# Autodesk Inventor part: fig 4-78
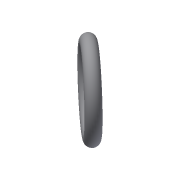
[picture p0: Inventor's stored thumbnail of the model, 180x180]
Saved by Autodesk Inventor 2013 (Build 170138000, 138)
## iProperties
Created: 2012-07
Part Number: fig 4-78
Material: Generic
Document SubType Name: Modeling
Designer: CADCIM
Density: 1 g/cm^3
Author: CADCIM
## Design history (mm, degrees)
sketch "Sketch1"
  geometry: L1 (-1.626, -1.876)-(1.626, 1.876); L2 (0, 0)-(7.504, -6.505); C1 r 1.845 at (7.504, -6.505)
  constraints: 4 end point, 1 centre point, 1 midpoint, 1 perpendicular
  dimensions: "d0" = 90 deg dimension on L2.end C1 L1.start L1.end L1 L2.start L2
revolve "Revolution1" sketch "Sketch1" stored, may be unused: angle "d0" = 90 deg
body "Solid1"
